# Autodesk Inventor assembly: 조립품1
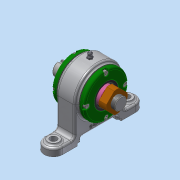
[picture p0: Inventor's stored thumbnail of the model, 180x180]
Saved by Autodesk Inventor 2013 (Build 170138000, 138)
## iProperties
Created: 2019-05
Part Number: 조립품1
Document SubType Name: Assembly
Designer: dgall
Author: dgall
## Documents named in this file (12)
- C:\Users\dgall\Desktop\490504V1053\조립품1.iam
- C:\Users\dgall\Desktop\490504V1053\개스킷.ipt
- C:\Users\dgall\Desktop\490504V1053\그리스니플 M6.ipt
- 그리스니플  M6.ipt
- C:\Users\dgall\Desktop\490504V1053\베어링너트.ipt
- C:\Users\dgall\Desktop\490504V1053\본체.ipt
- C:\Users\dgall\Desktop\490504V1053\볼트 M4.ipt
- C:\Users\dgall\Desktop\490504V1053\앵귤러 볼 베어링 7205.ipt
- C:\Users\dgall\Desktop\490504V1053\오일 실 28 40 5 B.ipt
- C:\Users\dgall\Desktop\490504V1053\축.ipt
- C:\Users\dgall\Desktop\490504V1053\칼라.ipt
- C:\Users\dgall\Desktop\490504V1053\커버.ipt
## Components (3 placed, 2 different names)
1. 개스킷:1
2. 그리스니플  M6:1
3. 개스킷:2
